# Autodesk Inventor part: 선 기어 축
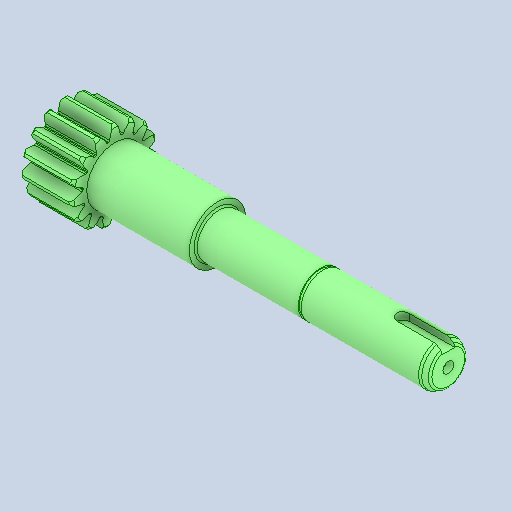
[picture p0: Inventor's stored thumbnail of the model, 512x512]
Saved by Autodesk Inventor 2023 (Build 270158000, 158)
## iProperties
Created: 2026-04
Part Number: 선 기어 축
Material: 강철, 합금
Document SubType Name: Modeling
Designer: home
Density: 7.73 g/cm^3
Appearance: 기본값
Author: jhkim
Sending System: Autodesk Inventor 2027
Preprocessor: ST-DEVELOPER v20.1
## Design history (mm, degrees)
feature "솔리드1"
node "솔리드2"
